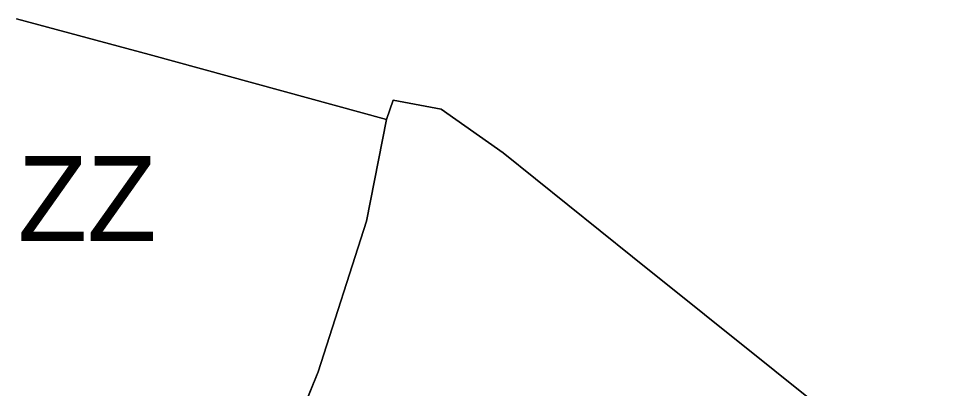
# Model space of a CAD drawing. Extents: x -555509 to -553005, y -1186756 to -1182560.
# Drawn here: x -554045.6 to -553890.2, y -1184312.3 to -1184251.5 of the extents above; entities that cross this region are included whole.
import ezdxf

# ---------------------------------------------------------------- set-up
doc = ezdxf.new("R2010")
doc.units = 0
for name, color, linetype in [('Level 36', 7, 'Continuous'), ('Level 52', 7, 'Continuous'), ('Level 59', 7, 'Continuous'), ('Level 6', 7, 'Continuous'), ('OBRYS_PLOCH', 7, 'Continuous'), ('stav_AP', 7, 'Continuous'), ('stav_VZ', 7, 'Continuous'), ('stav_ZZ', 7, 'Continuous')]:
    doc.layers.add(name, color=color, linetype=linetype)

msp = doc.modelspace()

# ---------------------------------------------------------------- linework, layer by layer
at = {"layer": 'Level 36'}
msp.add_lwpolyline([(-553909.03, -1184319), (-553944.41, -1184290.7), (-553965.73, -1184273.58), (-553975.95, -1184266.36), (-553983.89, -1184264.88), (-553984.98, -1184268.07), (-553988.28, -1184284.83), (-553996.23, -1184309.64), (-554006.09, -1184333.7)], dxfattribs=at)
at = {"layer": 'Level 52'}
msp.add_lwpolyline([(-553909.03, -1184319), (-553944.41, -1184290.7), (-553965.73, -1184273.58), (-553975.95, -1184266.36), (-553983.89, -1184264.88), (-553984.98, -1184268.07), (-553988.28, -1184284.83), (-553996.23, -1184309.64), (-554006.09, -1184333.7)], dxfattribs=at)
at = {"layer": 'Level 6'}
msp.add_lwpolyline([(-553909.03, -1184319), (-553944.41, -1184290.7), (-553965.73, -1184273.58), (-553975.95, -1184266.36), (-553983.89, -1184264.88), (-553984.98, -1184268.07), (-553988.28, -1184284.83), (-553996.23, -1184309.64), (-554006.09, -1184333.7)], dxfattribs=at)
at = {"layer": 'OBRYS_PLOCH'}
for p, q in [((-553983.89, -1184264.88), (-553984.98, -1184268.07)), ((-553984.98, -1184268.07), (-553983.89, -1184264.88)), ((-553988.28, -1184284.83), (-553984.98, -1184268.07)), ((-553984.98, -1184268.07), (-553988.28, -1184284.83)), ((-553944.41, -1184290.7), (-553965.73, -1184273.58)), ((-553996.23, -1184309.64), (-553988.28, -1184284.83)), ((-553988.28, -1184284.83), (-553996.23, -1184309.64)), ((-553996.23, -1184309.64), (-554006.09, -1184333.7))]:
    msp.add_line(p, q, dxfattribs=at)
for points in [[(-553984.98, -1184268.07), (-554024.09, -1184257.34), (-554046.02, -1184251.47)], [(-554046.02, -1184251.47), (-554024.09, -1184257.34), (-553984.98, -1184268.07)], [(-553965.73, -1184273.58), (-553975.95, -1184266.36), (-553983.89, -1184264.88)], [(-553983.89, -1184264.88), (-553975.95, -1184266.36), (-553965.73, -1184273.58)], [(-553965.73, -1184273.58), (-553944.41, -1184290.7), (-553909.03, -1184319)], [(-553890.19, -1184334.36), (-553909.03, -1184319), (-553944.41, -1184290.7)], [(-554009.7, -1184339.84), (-554007.16, -1184333.36), (-554006.09, -1184333.7), (-553996.23, -1184309.64)]]:
    msp.add_lwpolyline(points, dxfattribs=at)
at = {"layer": 'stav_AP'}
msp.add_line((-553984.98, -1184268.07), (-553983.89, -1184264.88), dxfattribs=at)
for points in [[(-554046.02, -1184251.47), (-554024.09, -1184257.34), (-553984.98, -1184268.07)], [(-553983.89, -1184264.88), (-553975.95, -1184266.36), (-553965.73, -1184273.58)], [(-553965.73, -1184273.58), (-553944.41, -1184290.7), (-553909.03, -1184319)]]:
    msp.add_lwpolyline(points, dxfattribs=at)
at = {"layer": 'stav_VZ'}
for p, q in [((-553983.89, -1184264.88), (-553984.98, -1184268.07)), ((-553984.98, -1184268.07), (-553988.28, -1184284.83)), ((-553944.41, -1184290.7), (-553965.73, -1184273.58)), ((-553988.28, -1184284.83), (-553996.23, -1184309.64)), ((-553996.23, -1184309.64), (-554006.09, -1184333.7))]:
    msp.add_line(p, q, dxfattribs=at)
for points in [[(-553965.73, -1184273.58), (-553975.95, -1184266.36), (-553983.89, -1184264.88)], [(-553890.19, -1184334.36), (-553909.03, -1184319), (-553944.41, -1184290.7)]]:
    msp.add_lwpolyline(points, dxfattribs=at)
at = {"layer": 'stav_ZZ'}
for p, q in [((-553988.28, -1184284.83), (-553984.98, -1184268.07)), ((-553996.23, -1184309.64), (-553988.28, -1184284.83))]:
    msp.add_line(p, q, dxfattribs=at)
for points in [[(-553984.98, -1184268.07), (-554024.09, -1184257.34), (-554046.02, -1184251.47)], [(-554009.7, -1184339.84), (-554007.16, -1184333.36), (-554006.09, -1184333.7), (-553996.23, -1184309.64)]]:
    msp.add_lwpolyline(points, dxfattribs=at)

# ---------------------------------------------------------------- texts
at = {"layer": 'Level 59'}
msp.add_text('ZZ', height=14, dxfattribs=at).set_placement((-554045.79, -1184288.1))

doc.saveas('drawing.dxf')
